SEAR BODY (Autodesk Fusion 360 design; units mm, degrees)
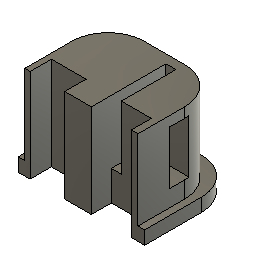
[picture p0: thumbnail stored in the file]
sketch "Sketch1" plane through (0, 0, 0) normal (0, 1, 0) x axis (1, 0, 0)
  line L1 (24, -5) -> (5, -5)
  line L2 (24, -19) -> (24, -5)
  line L3 (5, -19) -> (24, -19)
  line L4 (5, -5) -> (5, -19)
  point P2 (5, -5)
  point P3 (24, -5)
  point P5 (5, -19)
  horizontal L1
  vertical L2
  horizontal L3
  vertical L4
  dimension "d1" distance P2 P3 = 19
  dimension "d2" distance P2 P5 = 14
extrude "Extrude1" new body sketch "Sketch1" along normal blind 2
sketch "Sketch2" plane through (0, 2, 0) normal (0, 1, 0) x axis (-1, 0, 0)
  line L1 (-5, 5) -> (-24, 5)
  line L2 (-5, 19) -> (-5, 5)
  line L3 (-24, 19) -> (-5, 19)
  line L4 (-24, 5) -> (-24, 19)
  line L5 (-23, 19) -> (-6, 19)
  line L6 (-23, 6.5) -> (-23, 19)
  line L7 (-6, 6.5) -> (-23, 6.5)
  line L8 (-6, 19) -> (-6, 6.5)
  point P8 (-6, 19)
  point P9 (-23, 19)
  point P11 (-6, 6.5)
  horizontal L5
  vertical L6
  horizontal L7
  vertical L8
  coincident L3 P8
  dimension "d7" distance P8 P9 = 17
  dimension "d8" distance P8 P11 = 12.5
  dimension "d13" distance L2 L8 = 1
extrude "Extrude2" add sketch "Sketch2" profile of L3 L5 L6 L7 L8 along normal blind 12
fillet "Fillet1" radius 5.5 5.5 5.5 5.5
sketch "Sketch3" plane through (0, 14, 0) normal (0, 1, 0) x axis (-1, 0, 0)
  line L1 (-6, 19) -> (-6, 12)
  line L2 (-23, 19) -> (-6, 19)
  line L3 (-23, 12) -> (-23, 19)
  line L4 (-11.5, 6.5) -> (-17.5, 6.5)
  line L5 (-12, 19) -> (-6.8, 19)
  line L6 (-12, 15.8) -> (-12, 19)
  line L7 (-6.8, 15.8) -> (-12, 15.8)
  line L8 (-6.8, 19) -> (-6.8, 15.8)
  arc A1 centre (-11.5, 12) radius 5.5 clockwise from (-6, 12) to (-11.5, 6.5)
  arc A2 centre (-17.5, 12) radius 5.5 clockwise from (-17.5, 6.5) to (-23, 12)
  point P10 (-6.8, 19)
  point P11 (-12, 19)
  point P13 (-6.8, 15.8)
  horizontal L5
  vertical L6
  horizontal L7
  vertical L8
  coincident L2 P10
  dimension "d14" distance P10 P11 = 5.2
  dimension "d15" distance P10 P13 = 3.2
  dimension "d16" distance L1 L8 = 0.8
extrude "Extrude3" cut sketch "Sketch3" profile of L2 L5 L6 L7 L8 against normal blind 17
sketch "Sketch4" plane through (0, 14, 0) normal (0, 1, 0) x axis (-1, 0, 0)
  line L1 (-6.8, 15.8) -> (-6.8, 19)
  line L2 (-12, 15.8) -> (-6.8, 15.8)
  line L3 (-12, 19) -> (-12, 15.8)
  line L4 (-23, 19) -> (-12, 19)
  line L5 (-23, 12) -> (-23, 19)
  line L6 (-11.5, 6.5) -> (-17.5, 6.5)
  line L7 (-6, 19) -> (-6, 12)
  line L8 (-6.8, 19) -> (-6, 19)
  line L9 (-16, 19) -> (-22, 19)
  line L10 (-16, 16) -> (-16, 19)
  line L11 (-22, 16) -> (-16, 16)
  line L12 (-22, 19) -> (-22, 16)
  arc A1 centre (-17.5, 12) radius 5.5 clockwise from (-17.5, 6.5) to (-23, 12)
  arc A2 centre (-11.5, 12) radius 5.5 clockwise from (-6, 12) to (-11.5, 6.5)
  point P14 (-22, 19)
  point P15 (-16, 19)
  point P17 (-22, 16)
  horizontal L9
  vertical L10
  horizontal L11
  vertical L12
  coincident L4 P14
  dimension "d19" distance P14 P15 = 6
  dimension "d20" distance P14 P17 = 3
  dimension "d22" distance L5 L12 = 1
extrude "Extrude4" cut sketch "Sketch4" profile of L4 L9 L10 L11 L12 against normal blind 17
sketch "Sketch6" plane through (23, 0, 0) normal (1, 0, 0) x axis (0, 0, -1)
  line L1 (-12, 14) -> (-12, 2)
  line L2 (-19, 14) -> (-12, 14)
  line L3 (-19, 2) -> (-19, 14)
  line L4 (-12, 2) -> (-19, 2)
  line L5 (-11.3, 12.5) -> (-14.2, 12.5)
  line L6 (-11.3, 4.5) -> (-11.3, 12.5)
  line L7 (-14.2, 4.5) -> (-11.3, 4.5)
  line L8 (-14.2, 12.5) -> (-14.2, 4.5)
  point P6 (-14.2, 12.5)
  point P9 (-14.2, 4.5)
  point P7 (-11.3, 12.5)
  horizontal L5
  vertical L6
  horizontal L7
  vertical L8
  dimension "d29" distance P6 P9 = 8
  dimension "d30" distance P6 P7 = 2.9
  dimension "d31" distance L3 L8 = 4.8
  dimension "d41" distance L2 L5 = 1.5
extrude "Extrude6" cut sketch "Sketch6" profile of L5 L6 L7 L8 against normal blind 17
hole "Hole1" HoleDepth 1 HoleDiameter 8.5 TipAngle 180 RefDim1 5
sketch "Sketch7" plane through (0, 14, 0) normal (0, 1, 0) x axis (-1, 0, 0)
  line L1 (-22, 19) -> (-22, 16)
  line L2 (-23, 19) -> (-22, 19)
  line L3 (-23, 12) -> (-23, 19)
  line L4 (-11.5, 6.5) -> (-17.5, 6.5)
  line L5 (-6, 19) -> (-6, 12)
  line L6 (-6.8, 19) -> (-6, 19)
  line L7 (-6.8, 15.8) -> (-6.8, 19)
  line L8 (-12, 15.8) -> (-6.8, 15.8)
  line L9 (-12, 19) -> (-12, 15.8)
  line L10 (-16, 19) -> (-12, 19)
  line L11 (-16, 16) -> (-16, 19)
  line L12 (-22, 16) -> (-16, 16)
  line L13 (-17.5, 19) -> (-16, 19)
  line L14 (-17.5, 7.8) -> (-17.5, 19)
  line L15 (-16, 7.8) -> (-17.5, 7.8)
  line L16 (-16, 19) -> (-16, 7.8)
  arc A1 centre (-17.5, 12) radius 5.5 clockwise from (-17.5, 6.5) to (-23, 12)
  arc A2 centre (-11.5, 12) radius 5.5 clockwise from (-6, 12) to (-11.5, 6.5)
  point P16 (-16, 19)
  point P18 (-16, 19)
  point P21 (-16, 7.8)
  point P19 (-17.5, 19)
  horizontal L13
  vertical L14
  horizontal L15
  vertical L16
  coincident P16 P18
  dimension "d42" distance P18 P21 = 11.2
  dimension "d43" distance P18 P19 = 1.5
extrude "Extrude7" cut sketch "Sketch7" profile of L12 L14 L15 L16 against normal blind 9.5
